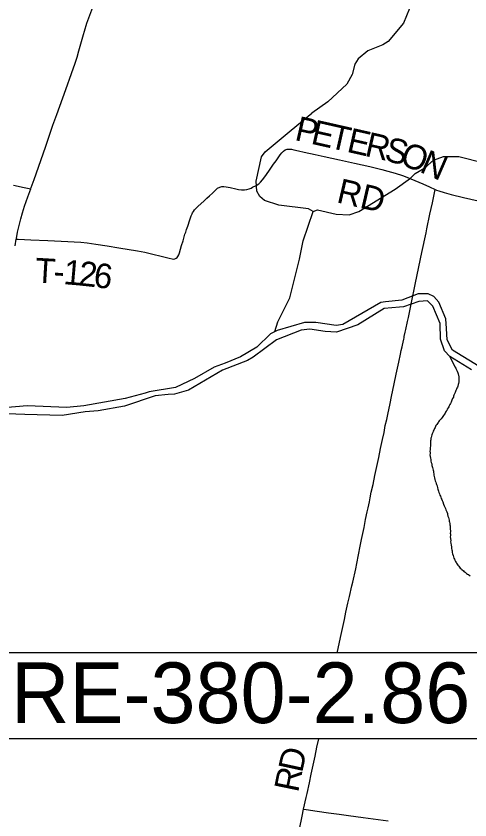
# Model space of a CAD drawing. Extents: x 0 to 34, y 0 to 22.
# Drawn here: x 12.342 to 13.391, y 17.083 to 18.939 of the extents above; entities that cross this region are included whole.
import ezdxf

# ---------------------------------------------------------------- set-up
doc = ezdxf.new("R2010")
doc.units = 0
for name, color, linetype in [('GM_X_County_Road', 7, 'Continuous'), ('GM_X_County_Road_Text', 7, 'Continuous'), ('GM_X_Major_River', 7, 'Continuous'), ('GM_X_Minor_River', 7, 'Continuous'), ('GM_X_State_Route', 7, 'Continuous'), ('GM_X_Township_Road', 7, 'Continuous'), ('GM_X_Township_Road_Text', 7, 'Continuous'), ('SH_Text', 7, 'Continuous')]:
    doc.layers.add(name, color=color, linetype=linetype)

msp = doc.modelspace()

# ---------------------------------------------------------------- linework, layer by layer
at = {"layer": 'GM_X_County_Road'}
for points in [[(13.0847, 17.47), (13.0851, 17.4722), (13.0934, 17.5111), (13.0964, 17.525), (13.101, 17.5463), (13.1047, 17.5632), (13.1092, 17.5838), (13.1128, 17.5993), (13.1184, 17.6236), (13.1203, 17.632), (13.1271, 17.663), (13.1296, 17.6757), (13.1377, 17.7153), (13.1407, 17.7311), (13.1436, 17.745), (13.1463, 17.7585), (13.15, 17.7767), (13.154, 17.7949), (13.1559, 17.804), (13.1588, 17.8179), (13.1606, 17.8271), (13.1632, 17.8398), (13.1671, 17.858), (13.1714, 17.8782), (13.1759, 17.8993), (13.1803, 17.92), (13.1848, 17.9412), (13.1892, 17.9613), (13.1926, 17.9777), (13.1956, 17.9936), (13.1988, 18.0075), (13.2013, 18.019), (13.2068, 18.0445), (13.21, 18.061), (13.2157, 18.0901), (13.2204, 18.1125), (13.2236, 18.1264), (13.2268, 18.1403), (13.2307, 18.1585), (13.2325, 18.1669), (13.2343, 18.1754), (13.2352, 18.1797), (13.2382, 18.1936), (13.2388, 18.1965), (13.2395, 18.1995), (13.2417, 18.2098), (13.243, 18.2159), (13.2469, 18.2341), (13.2488, 18.2432), (13.2583, 18.2895), (13.2623, 18.3083), (13.2646, 18.3192), (13.2694, 18.3417), (13.2801, 18.3934), (13.2897, 18.4384), (13.2917, 18.4481), (13.2988, 18.4822), (13.3043, 18.5077), (13.3105, 18.5387)], [(13.3105, 18.5387), (13.3136, 18.5376), (13.3189, 18.5356), (13.3313, 18.5316), (13.3475, 18.5271), (13.3759, 18.5203), (13.4099, 18.5127), (13.4324, 18.5079), (13.4493, 18.504), (13.4625, 18.5009), (13.4821, 18.4963), (13.4885, 18.4948)], [(13.0067, 17.1083), (13.0126, 17.1352), (13.0147, 17.1443), (13.02, 17.1692), (13.0244, 17.1892), (13.0332, 17.2305), (13.0376, 17.2512), (13.0418, 17.2706)], [(12.8726, 16.5287), (12.8803, 16.559), (12.8858, 16.58), (12.8919, 16.6027), (12.9084, 16.6639), (12.9215, 16.7138), (12.9277, 16.7392), (12.9338, 16.7657), (12.9383, 16.7865), (12.9445, 16.8164), (12.9512, 16.8485), (12.9608, 16.8935), (12.9631, 16.9044), (12.9678, 16.9263), (12.9743, 16.9566), (12.9831, 16.9967), (12.9895, 17.0258), (12.994, 17.0471), (12.9971, 17.0623), (13.0032, 17.0921), (13.0067, 17.1083)], [(13.0067, 17.1083), (13.0129, 17.1073), (13.0381, 17.1036), (13.0639, 17.1), (13.0891, 17.0966), (13.1107, 17.0938), (13.1445, 17.089), (13.2024, 17.0814)]]:
    msp.add_lwpolyline(points, dxfattribs=at)
at = {"layer": 'GM_X_Major_River'}
for points in [[(13.4124, 18.1298), (13.3509, 18.1677), (13.3382, 18.1915), (13.3373, 18.2178), (13.3351, 18.2403), (13.3189, 18.2786), (13.3078, 18.2914), (13.2946, 18.2978), (13.2714, 18.298), (13.2338, 18.2833), (13.1957, 18.2796), (13.1851, 18.2783), (13.0976, 18.2275), (13.082, 18.2252), (13.035, 18.232), (13.0087, 18.2315), (12.9456, 18.2135), (12.9306, 18.2055), (12.8983, 18.1751), (12.861, 18.1528), (12.8253, 18.1377), (12.7999, 18.1284), (12.7549, 18.1024), (12.7107, 18.0818), (12.65, 18.0714), (12.6404, 18.0686), (12.5941, 18.056), (12.4991, 18.0395), (12.4599, 18.0359), (12.3676, 18.0392), (12.3143, 18.0351)], [(13.3951, 18.1222), (13.3449, 18.1534), (13.3323, 18.1666), (13.323, 18.1934), (13.3227, 18.2291), (13.305, 18.2698), (13.2931, 18.2815), (13.2733, 18.2805), (13.2377, 18.268), (13.2282, 18.2674), (13.1931, 18.2641), (13.1318, 18.226), (13.0831, 18.2092), (13.0565, 18.2106), (13.0213, 18.2167), (13.0011, 18.2142), (12.9443, 18.1919), (12.8898, 18.1521), (12.8767, 18.1437), (12.8196, 18.1218), (12.7409, 18.0754), (12.708, 18.0662), (12.694, 18.0658), (12.6639, 18.0627), (12.593, 18.0385), (12.5323, 18.0277), (12.5022, 18.0258), (12.4488, 18.0167), (12.3625, 18.0191), (12.2786, 18.0222)]]:
    msp.add_lwpolyline(points, dxfattribs=at)
at = {"layer": 'GM_X_Minor_River'}
for points in [[(13.4085, 19.1546), (13.3844, 19.1494), (13.3637, 19.1368), (13.3579, 19.1263), (13.3576, 19.0921), (13.3544, 19.0804), (13.3343, 19.0595), (13.3216, 19.0263), (13.3114, 19.0063), (13.3028, 18.9959), (13.2917, 18.9885), (13.2851, 18.9772), (13.2517, 18.9565), (13.2374, 18.9229), (13.2025, 18.8806), (13.1895, 18.8725), (13.1551, 18.8587), (13.1331, 18.8404), (13.1249, 18.828), (13.1192, 18.8046), (13.1067, 18.782), (13.0631, 18.741), (13.0258, 18.7151)], [(13.0287, 18.4879), (13.0177, 18.4942), (12.9492, 18.503), (12.916, 18.5133), (12.9052, 18.523), (12.8987, 18.5346), (12.8969, 18.5582), (12.9095, 18.6145), (12.9177, 18.6257), (12.9776, 18.6759), (13.0258, 18.7151)], [(12.9404, 18.2108), (12.9469, 18.233), (12.975, 18.2885), (12.9974, 18.3777), (13.0059, 18.42), (13.0286, 18.4879), (13.0389, 18.4922), (13.0823, 18.482), (13.1119, 18.4802), (13.1341, 18.488), (13.2186, 18.5392), (13.2541, 18.565), (13.2646, 18.5761), (13.2872, 18.5885), (13.307, 18.6067), (13.3299, 18.6153), (13.3652, 18.6148), (13.423, 18.6005), (13.4343, 18.5968), (13.4717, 18.5888), (13.4834, 18.5889), (13.4938, 18.5932), (13.5083, 18.6164), (13.5201, 18.7048)], [(13.3449, 18.1534), (13.3561, 18.1296), (13.3583, 18.1262), (13.3595, 18.1239), (13.3617, 18.1197), (13.3628, 18.1159), (13.3643, 18.1132), (13.3654, 18.1064), (13.3654, 18.1029), (13.3658, 18.0991), (13.3654, 18.0969), (13.3654, 18.095), (13.3646, 18.0912), (13.3642, 18.0885), (13.3634, 18.0851), (13.3626, 18.0828), (13.3611, 18.0802), (13.3603, 18.0779), (13.3588, 18.0749), (13.3576, 18.0722), (13.3568, 18.0699), (13.3557, 18.0673), (13.3541, 18.0639), (13.3534, 18.062), (13.353, 18.0597), (13.351, 18.0563), (13.3503, 18.0544), (13.3483, 18.0502), (13.3476, 18.0476), (13.346, 18.0449), (13.3445, 18.0423), (13.3433, 18.0396), (13.3422, 18.0374), (13.3406, 18.0347), (13.3387, 18.0313), (13.3375, 18.0286), (13.3364, 18.0268), (13.3349, 18.0249), (13.3337, 18.0226), (13.3322, 18.0199), (13.3302, 18.0173), (13.3283, 18.0147), (13.3272, 18.0124), (13.3249, 18.0097), (13.323, 18.0075), (13.3203, 18.0044), (13.3187, 18.0026), (13.3176, 18.0007), (13.3145, 17.9965), (13.3126, 17.9939), (13.3118, 17.992), (13.3107, 17.9897), (13.3091, 17.9874), (13.3084, 17.9855), (13.308, 17.9833), (13.3064, 17.9806), (13.3053, 17.9779), (13.3041, 17.9749), (13.3033, 17.9723), (13.3022, 17.9696), (13.3014, 17.9666), (13.3006, 17.9647), (13.3006, 17.9628), (13.3006, 17.9609), (13.2998, 17.9586), (13.2998, 17.9563), (13.2998, 17.9544), (13.2998, 17.9518), (13.2997, 17.9487), (13.2997, 17.9461), (13.2993, 17.943), (13.2989, 17.9404), (13.2989, 17.9385), (13.2985, 17.9343), (13.2989, 17.9324), (13.2992, 17.9297), (13.2988, 17.9263), (13.2992, 17.9221), (13.2999, 17.9183), (13.3007, 17.9156), (13.301, 17.9118), (13.3018, 17.9084), (13.3029, 17.9054), (13.3032, 17.9019), (13.304, 17.8997), (13.3047, 17.897), (13.3055, 17.8943), (13.3058, 17.8909), (13.3066, 17.8886), (13.308, 17.8795), (13.3084, 17.8764), (13.3091, 17.8734), (13.3099, 17.8696), (13.311, 17.8665), (13.3121, 17.8631), (13.3132, 17.8604), (13.314, 17.8574), (13.3151, 17.8543), (13.3162, 17.8502), (13.3173, 17.8467), (13.3184, 17.8425)], [(13.3184, 17.8425), (13.3195, 17.8391), (13.321, 17.8361), (13.3214, 17.833), (13.3229, 17.8307), (13.324, 17.8284), (13.3248, 17.8258), (13.3259, 17.8235), (13.327, 17.8208), (13.3281, 17.8174), (13.3304, 17.8124), (13.3319, 17.8086), (13.3334, 17.8056), (13.3345, 17.8025), (13.3356, 17.7995), (13.3371, 17.7964), (13.3375, 17.7945), (13.339, 17.7911), (13.3394, 17.7884), (13.3401, 17.785), (13.3416, 17.7816), (13.3423, 17.7785), (13.3431, 17.7755), (13.3434, 17.7728), (13.3442, 17.7705), (13.3445, 17.7679), (13.3449, 17.7648), (13.3453, 17.7625), (13.3456, 17.7602), (13.3456, 17.7572), (13.3456, 17.7545), (13.3459, 17.7511), (13.3459, 17.7488), (13.3455, 17.7454), (13.3459, 17.7428), (13.3462, 17.7401), (13.3458, 17.7371), (13.3469, 17.7287), (13.3465, 17.7256), (13.3473, 17.7222), (13.3476, 17.7177), (13.3484, 17.7139), (13.3483, 17.71), (13.3491, 17.707), (13.3498, 17.7043), (13.3498, 17.7005), (13.3509, 17.6975), (13.352, 17.6941), (13.3528, 17.691), (13.3539, 17.6876), (13.3554, 17.6853), (13.3565, 17.683), (13.358, 17.6803), (13.3591, 17.678), (13.3603, 17.6761), (13.3618, 17.6738), (13.3629, 17.6712), (13.3652, 17.6689), (13.367, 17.6666), (13.3689, 17.6647), (13.3708, 17.6628), (13.3727, 17.6612), (13.3761, 17.6582), (13.378, 17.6562), (13.3799, 17.6551), (13.3818, 17.6539), (13.3833, 17.652), (13.3856, 17.6509), (13.3878, 17.6497), (13.3913, 17.647)]]:
    msp.add_lwpolyline(points, dxfattribs=at)
at = {"layer": 'GM_X_State_Route'}
for points in [[(12.3771, 18.5431), (12.3839, 18.5621), (12.41, 18.6365), (12.4189, 18.6623), (12.4275, 18.687), (12.4362, 18.7116), (12.457, 18.7694), (12.4704, 18.8068), (12.4786, 18.8302), (12.4832, 18.8443), (12.4873, 18.8586), (12.492, 18.8754), (12.4979, 18.8963), (12.5004, 18.9047), (12.506, 18.9231), (12.5103, 18.9354), (12.5195, 18.9599)], [(12.3402, 18.4087), (12.3427, 18.4244), (12.3429, 18.4259), (12.3456, 18.44), (12.3491, 18.4558), (12.3529, 18.4708), (12.357, 18.4852), (12.3618, 18.5), (12.3693, 18.5217), (12.376, 18.5403), (12.3771, 18.5431)]]:
    msp.add_lwpolyline(points, dxfattribs=at)
at = {"layer": 'GM_X_Township_Road'}
for points in [[(12.3427, 18.4244), (12.3469, 18.4241), (12.3766, 18.4226), (12.4157, 18.4209), (12.4468, 18.4194), (12.492, 18.4169), (12.5069, 18.4156), (12.5265, 18.4129), (12.5529, 18.4087), (12.5799, 18.4044), (12.6228, 18.3974), (12.6399, 18.3943), (12.652, 18.3914), (12.6838, 18.3831), (12.6958, 18.38), (12.7026, 18.3784), (12.7059, 18.3783), (12.7092, 18.3789), (12.7122, 18.3804), (12.7142, 18.382), (12.7164, 18.3845), (12.7183, 18.3879), (12.72, 18.3927), (12.7248, 18.4098), (12.7281, 18.4204), (12.7326, 18.4355), (12.7342, 18.4402), (12.7361, 18.4461), (12.7389, 18.4544), (12.7438, 18.4691), (12.7469, 18.4778), (12.7491, 18.4828), (12.7503, 18.4852), (12.7521, 18.4881), (12.7549, 18.4921), (12.7574, 18.495), (12.7627, 18.5002), (12.7762, 18.5122), (12.7831, 18.5184), (12.7895, 18.5241), (12.7964, 18.5307), (12.8, 18.5341), (12.8026, 18.5368), (12.8081, 18.5416), (12.8132, 18.5445), (12.8179, 18.5456), (12.822, 18.5458), (12.8275, 18.5453), (12.8372, 18.5435), (12.8499, 18.5407), (12.8566, 18.5391), (12.8629, 18.5381), (12.8698, 18.5378), (12.8755, 18.5388), (12.8809, 18.5403), (12.8856, 18.5422), (12.889, 18.5438), (12.8974, 18.5481), (12.9031, 18.5521), (12.9074, 18.5559), (12.9119, 18.5611), (12.9171, 18.5681), (12.9266, 18.5813), (12.9375, 18.5971), (12.9433, 18.6051), (12.9527, 18.6191), (12.9565, 18.6238), (12.9604, 18.6276), (12.9644, 18.6301), (12.9689, 18.6316), (12.9737, 18.632), (12.9785, 18.6316), (12.9845, 18.6304), (12.9948, 18.6281), (13.0081, 18.6251), (13.0338, 18.6194), (13.0544, 18.615), (13.0896, 18.607), (13.1242, 18.5994), (13.1594, 18.5916), (13.1878, 18.585), (13.2016, 18.5815), (13.2182, 18.5766), (13.2354, 18.571), (13.2452, 18.5674), (13.2819, 18.552), (13.2977, 18.5449), (13.3105, 18.5387)], [(12.3364, 18.5486), (12.3613, 18.5436), (12.3728, 18.541), (12.376, 18.5403)]]:
    msp.add_lwpolyline(points, dxfattribs=at)
at = {"layer": 'SH_Text'}
msp.add_lwpolyline([(12.1731, 17.47), (13.4915, 17.47), (13.4915, 17.2706), (12.1731, 17.2706)], close=True, dxfattribs=at)

# ---------------------------------------------------------------- texts
at = {"layer": 'GM_X_County_Road_Text'}
for s, rotation, p in [('D', 77.7248, (13.0032, 17.1907)), ('R', 78.3357, (12.9938, 17.1452))]:
    msp.add_text(s, height=0.0568, rotation=rotation, dxfattribs=at).set_placement(p)
at = {"layer": 'GM_X_Township_Road_Text'}
for s, height, rotation, p in [('P', 0.0568, 347.2903, (12.9841, 18.6533)), ('E', 0.0568, 347.2881, (13.0215, 18.6449)), ('T', 0.0568, 347.2902, (13.063, 18.6355)), ('E', 0.0568, 347.2881, (13.1044, 18.6262)), ('R', 0.0568, 347.1414, (13.1459, 18.6168)), ('S', 0.0568, 345.255, (13.1909, 18.6066)), ('O', 0.0568, 339.5279, (13.2265, 18.5973)), ('N', 0.0568, 336.4599, (13.2726, 18.5801)), ('RD', 0.05682, 346.8961, (13.0807, 18.5096)), ('T', 0.0568, 356.6381, (12.3851, 18.3245)), ('1', 0.0568, 355.191, (12.4504, 18.3205)), ('2', 0.0568, 353.9311, (12.485, 18.3176)), ('6', 0.0568, 352.6529, (12.5194, 18.314)), ('-', 0.0568, 356.2269, (12.4274, 18.322))]:
    msp.add_text(s, height=height, rotation=rotation, dxfattribs=at).set_placement(p)
at = {"layer": 'SH_Text'}
msp.add_text('GRE-380-2.86', height=0.14, dxfattribs=at).set_placement((12.1848, 17.307))

doc.saveas('drawing.dxf')
